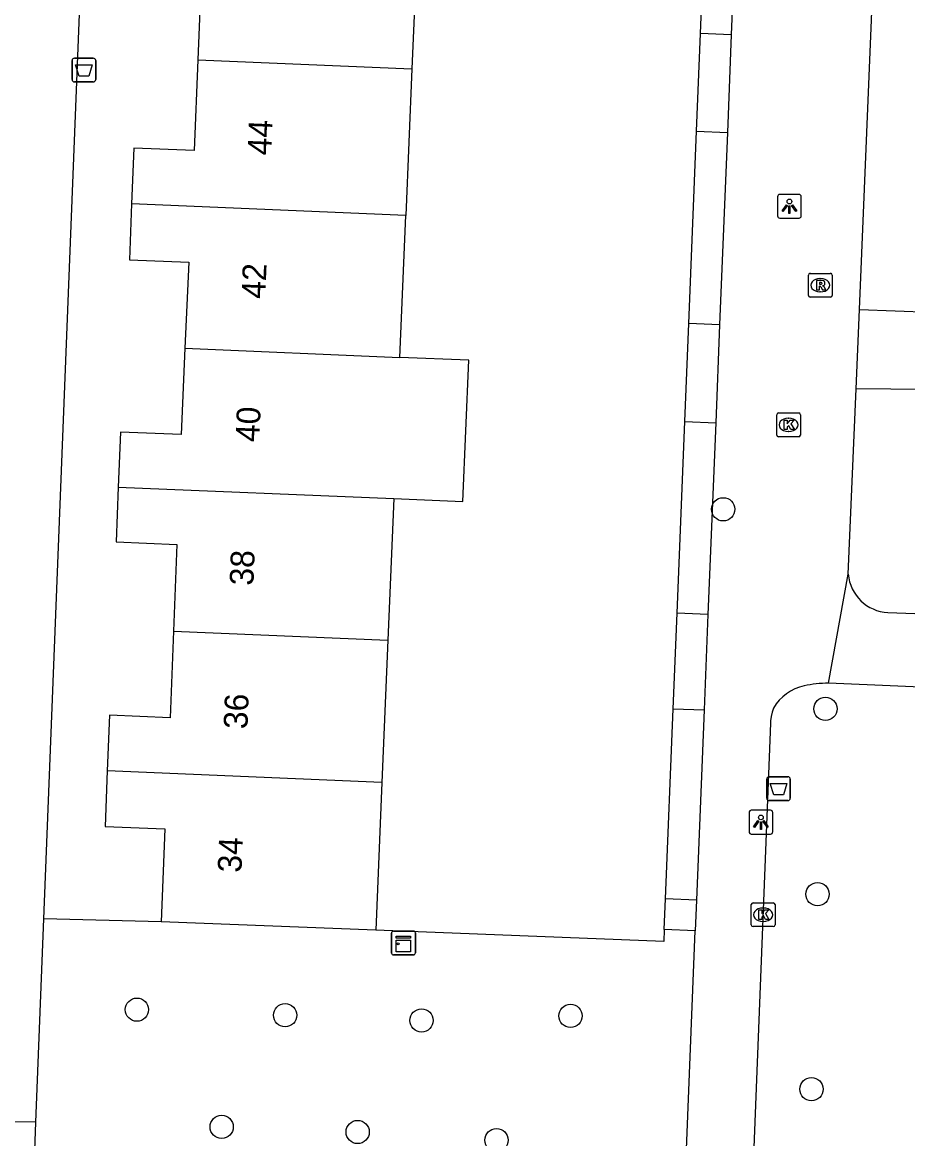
# Model space of a CAD drawing. Extents: x 160787 to 161428, y 386828 to 387483.
# Drawn here: x 161103.85 to 161141.08, y 387264.64 to 387311.59 of the extents above; entities that cross this region are included whole.
import ezdxf

# ---------------------------------------------------------------- set-up
doc = ezdxf.new("R2010")
doc.units = 0
for name, color, linetype in [('IMGEO_Afvalbak', 7, 'Continuous'), ('IMGEO_Boom', 7, 'Continuous'), ('IMGEO_Groenvoorziening', 7, 'Continuous'), ('IMGEO_Haag', 7, 'Continuous'), ('IMGEO_Kast', 7, 'Continuous'), ('IMGEO_Kolk', 7, 'Continuous'), ('IMGEO_Lichtpunt', 7, 'Continuous'), ('IMGEO_Pand', 7, 'Continuous'), ('IMGEO_Pand_nummerreeks', 7, 'Continuous'), ('IMGEO_Rioolput', 7, 'Continuous'), ('IMGEO_Voetpad_open', 7, 'Continuous')]:
    doc.layers.add(name, color=color, linetype=linetype)

msp = doc.modelspace()

# ---------------------------------------------------------------- linework, layer by layer
at = {"layer": 'IMGEO_Afvalbak'}
for p, q in [((161105.946, 387309.18), (161105.946, 387309.98)), ((161105.946, 387309.98), (161105.946, 387309.18)), ((161106.046, 387310.08), (161106.836, 387310.08)), ((161106.836, 387310.08), (161106.046, 387310.08)), ((161106.936, 387309.98), (161106.936, 387309.18)), ((161106.936, 387309.18), (161106.936, 387309.98)), ((161106.836, 387309.08), (161106.046, 387309.08)), ((161106.046, 387309.08), (161106.836, 387309.08)), ((161135.153, 387278.962), (161135.153, 387279.762)), ((161135.153, 387279.762), (161135.153, 387278.962)), ((161135.253, 387279.862), (161136.043, 387279.862)), ((161136.043, 387279.862), (161135.253, 387279.862)), ((161136.143, 387279.762), (161136.143, 387278.962)), ((161136.143, 387278.962), (161136.143, 387279.762)), ((161136.043, 387278.862), (161135.253, 387278.862)), ((161135.253, 387278.862), (161136.043, 387278.862))]:
    msp.add_line(p, q, dxfattribs=at)
for points in [[(161106.089, 387309.794), (161106.793, 387309.794), (161106.644, 387309.324), (161106.238, 387309.324), (161106.089, 387309.794)], [(161135.296, 387279.576), (161136, 387279.576), (161135.851, 387279.106), (161135.445, 387279.106), (161135.296, 387279.576)]]:
    msp.add_lwpolyline(points, dxfattribs=at)
for centre, start, end in [((161106.046, 387309.98), 90, 180), ((161106.046, 387309.98), 90, 180), ((161106.836, 387309.98), 0, 90), ((161106.836, 387309.98), 360, 90), ((161106.046, 387309.18), 180, 270), ((161106.046, 387309.18), 180, 270), ((161106.836, 387309.18), 270, 0), ((161106.836, 387309.18), 270, 0), ((161135.253, 387279.762), 90, 180), ((161135.253, 387279.762), 90, 180), ((161136.043, 387279.762), 0, 90), ((161136.043, 387279.762), 360, 90), ((161135.253, 387278.962), 180, 270), ((161135.253, 387278.962), 180, 270), ((161136.043, 387278.962), 270, 0), ((161136.043, 387278.962), 270, 0)]:
    msp.add_arc(centre, 0.1, start, end, dxfattribs=at)
at = {"layer": 'IMGEO_Boom'}
for centre in [(161133.321, 387291.109), (161137.619, 387282.717), (161137.288, 387274.923), (161108.67, 387270.067), (161114.902, 387269.831), (161120.638, 387269.615), (161126.901, 387269.805), (161137.032, 387266.723), (161112.233, 387265.138), (161117.951, 387264.922), (161123.79, 387264.578)]:
    msp.add_circle(centre, 0.489, dxfattribs=at)
at = {"layer": 'IMGEO_Groenvoorziening'}
for points in [[(161139.046, 387299.512), (161143.553, 387299.341), (161151.391, 387299.041)], [(161164.993, 387293.208), (161158.958, 387293.171), (161155.006, 387296.014), (161138.908, 387296.177)], [(161109.694, 387273.762), (161104.756, 387273.893)], [(161130.846, 387273.44), (161130.826, 387272.934), (161118.71, 387273.409)]]:
    msp.add_lwpolyline(points, dxfattribs=at)
at = {"layer": 'IMGEO_Haag'}
for points in [[(161132.363, 387311.119), (161132.69, 387319.253)], [(161131.872, 387298.919), (161132.197, 387307.013)], [(161131.382, 387286.74), (161131.706, 387294.803)], [(161130.898, 387274.729), (161131.22, 387282.723)]]:
    msp.add_lwpolyline(points, dxfattribs=at)
at = {"layer": 'IMGEO_Kast'}
for p, q in [((161119.377, 387272.447), (161119.377, 387273.288)), ((161119.377, 387273.288), (161119.377, 387272.447)), ((161119.452, 387273.372), (161120.293, 387273.372)), ((161120.293, 387273.372), (161119.452, 387273.372)), ((161120.377, 387273.297), (161120.377, 387272.456)), ((161120.377, 387272.456), (161120.377, 387273.297)), ((161120.302, 387272.372), (161119.461, 387272.372)), ((161119.461, 387272.372), (161120.302, 387272.372))]:
    msp.add_line(p, q, dxfattribs=at)
for points in [[(161119.572, 387273.162), (161120.172, 387273.162), (161120.172, 387273.077), (161119.572, 387273.077), (161119.572, 387273.162)], [(161119.572, 387272.987), (161120.172, 387272.987), (161120.172, 387272.498), (161119.572, 387272.498), (161119.572, 387272.987)]]:
    msp.add_lwpolyline(points, dxfattribs=at)
msp.add_circle((161119.656, 387272.836), 0.0377, dxfattribs=at)
for centre, start, end in [((161119.455, 387273.294), 92.4484, 184.2845), ((161119.455, 387273.294), 92.4484, 184.2845), ((161120.299, 387273.294), 2.4484, 94.2845), ((161120.299, 387273.294), 2.4484, 94.2845), ((161119.455, 387272.45), 182.4484, 274.2845), ((161119.455, 387272.45), 182.4484, 274.2845), ((161120.299, 387272.45), 272.4484, 4.2845), ((161120.299, 387272.45), 272.4484, 4.2845)]:
    msp.add_arc(centre, 0.0779, start, end, dxfattribs=at)
at = {"layer": 'IMGEO_Kolk'}
for p, q in [((161135.57, 387294.233), (161135.57, 387295.085)), ((161135.645, 387295.159), (161136.497, 387295.159)), ((161136.058, 387294.939), (161136.083, 387294.939)), ((161136.571, 387295.085), (161136.571, 387294.233)), ((161136.081, 387294.379), (161136.056, 387294.379)), ((161136.497, 387294.159), (161135.645, 387294.159)), ((161134.576, 387274.559), (161135.428, 387274.559)), ((161134.501, 387273.633), (161134.501, 387274.485)), ((161134.989, 387274.339), (161135.014, 387274.339)), ((161135.502, 387274.485), (161135.502, 387273.633)), ((161135.012, 387273.779), (161134.987, 387273.779)), ((161135.428, 387273.559), (161134.576, 387273.559))]:
    msp.add_line(p, q, dxfattribs=at)
for points in [[(161135.57, 387294.233), (161135.57, 387295.085)], [(161135.645, 387295.159), (161136.497, 387295.159)], [(161135.891, 387294.859), (161136.014, 387294.859), (161136.014, 387294.708), (161136.144, 387294.859), (161136.308, 387294.859), (161136.162, 387294.708), (161136.315, 387294.459), (161136.163, 387294.459), (161136.078, 387294.623), (161136.014, 387294.556), (161136.014, 387294.459), (161135.891, 387294.459), (161135.891, 387294.859)], [(161136.571, 387295.085), (161136.571, 387294.233)], [(161136.497, 387294.159), (161135.645, 387294.159)], [(161134.576, 387274.559), (161135.428, 387274.559)], [(161134.501, 387273.633), (161134.501, 387274.485)], [(161134.822, 387274.259), (161134.945, 387274.259), (161134.945, 387274.108), (161135.075, 387274.259), (161135.239, 387274.259), (161135.093, 387274.108), (161135.246, 387273.859), (161135.094, 387273.859), (161135.009, 387274.023), (161134.945, 387273.956), (161134.945, 387273.859), (161134.822, 387273.859), (161134.822, 387274.259)], [(161135.502, 387274.485), (161135.502, 387273.633)], [(161135.428, 387273.559), (161134.576, 387273.559)]]:
    msp.add_lwpolyline(points, dxfattribs=at)
for centre, start, end in [((161135.647, 387295.083), 91.552, 178.448), ((161135.647, 387295.083), 91.552, 178.448), ((161136.495, 387295.083), 1.552, 88.448), ((161136.495, 387295.083), 1.552, 88.448), ((161135.647, 387294.235), 181.552, 268.448), ((161135.647, 387294.235), 181.552, 268.448), ((161136.495, 387294.235), 271.552, 358.448), ((161136.495, 387294.235), 271.552, 358.448), ((161134.578, 387274.483), 91.552, 178.448), ((161134.578, 387274.483), 91.552, 178.448), ((161135.426, 387274.483), 1.552, 88.448), ((161135.426, 387274.483), 1.552, 88.448), ((161134.578, 387273.635), 181.552, 268.448), ((161134.578, 387273.635), 181.552, 268.448), ((161135.426, 387273.635), 271.552, 358.448), ((161135.426, 387273.635), 271.552, 358.448)]:
    msp.add_arc(centre, 0.0765, start, end, dxfattribs=at)
for centre, major_axis, ratio, start_param, end_param in [((161136.057, 387294.659), (-0.387, 0.002), 0.722429, 4.712389, 7.853982), ((161136.082, 387294.659), (-0.39, 0.002), 0.717154, 1.570796, 4.712389), ((161134.988, 387274.059), (-0.387, 0.002), 0.722429, 4.712389, 7.853982), ((161135.013, 387274.059), (-0.39, 0.002), 0.717154, 1.570796, 4.712389)]:
    msp.add_ellipse(centre, major_axis=major_axis, ratio=ratio, start_param=start_param, end_param=end_param, dxfattribs=at)
at = {"layer": 'IMGEO_Lichtpunt'}
for p, q in [((161135.607, 387304.255), (161135.607, 387303.448)), ((161135.607, 387304.255), (161135.607, 387303.448)), ((161136.509, 387304.35), (161135.701, 387304.35)), ((161136.509, 387304.35), (161135.701, 387304.35)), ((161136.603, 387303.448), (161136.603, 387304.255)), ((161136.603, 387303.448), (161136.603, 387304.255)), ((161135.701, 387303.354), (161136.509, 387303.354)), ((161135.701, 387303.354), (161136.509, 387303.354)), ((161134.408, 387278.355), (161134.408, 387277.548)), ((161134.408, 387278.355), (161134.408, 387277.548)), ((161135.31, 387278.45), (161134.502, 387278.45)), ((161135.31, 387278.45), (161134.502, 387278.45)), ((161135.404, 387277.548), (161135.404, 387278.355)), ((161135.404, 387277.548), (161135.404, 387278.355)), ((161134.502, 387277.454), (161135.31, 387277.454)), ((161134.502, 387277.454), (161135.31, 387277.454))]:
    msp.add_line(p, q, dxfattribs=at)
for points in [[(161135.981, 387303.919), (161136.02, 387303.891), (161135.832, 387303.629), (161135.794, 387303.656), (161135.981, 387303.919)], [(161136.083, 387303.871), (161136.13, 387303.871), (161136.13, 387303.549), (161136.083, 387303.549), (161136.083, 387303.871)], [(161136.193, 387303.891), (161136.231, 387303.918), (161136.418, 387303.656), (161136.379, 387303.628), (161136.193, 387303.891)], [(161134.782, 387278.019), (161134.821, 387277.991), (161134.633, 387277.729), (161134.595, 387277.756), (161134.782, 387278.019)], [(161134.884, 387277.971), (161134.931, 387277.971), (161134.931, 387277.649), (161134.884, 387277.649), (161134.884, 387277.971)], [(161134.994, 387277.991), (161135.032, 387278.018), (161135.219, 387277.756), (161135.18, 387277.728), (161134.994, 387277.991)]]:
    msp.add_lwpolyline(points, dxfattribs=at)
for centre in [(161136.106, 387304.053), (161134.907, 387278.153)]:
    msp.add_circle(centre, 0.0994, dxfattribs=at)
for centre, start, end in [((161135.701, 387304.255), 90, 180), ((161135.701, 387304.255), 90, 180), ((161136.509, 387304.255), 0, 90), ((161136.509, 387304.255), 0, 90), ((161135.701, 387303.448), 180, 270), ((161135.701, 387303.448), 180, 270), ((161136.509, 387303.448), 270, 0), ((161136.509, 387303.448), 270, 360), ((161134.502, 387278.355), 90, 180), ((161134.502, 387278.355), 90, 180), ((161135.31, 387278.355), 0, 90), ((161135.31, 387278.355), 0, 90), ((161134.502, 387277.548), 180, 270), ((161134.502, 387277.548), 180, 270), ((161135.31, 387277.548), 270, 0), ((161135.31, 387277.548), 270, 360)]:
    msp.add_arc(centre, 0.0946, start, end, dxfattribs=at)
at = {"layer": 'IMGEO_Pand'}
for points in [[(161108.982, 387316.222), (161108.89, 387313.938), (161111.382, 387313.838), (161111.228, 387310.015)], [(161120.493, 387315.737), (161120.236, 387309.635)], [(161111.228, 387310.015), (161111.074, 387306.191), (161108.542, 387306.293), (161108.448, 387303.95)], [(161111.228, 387310.015), (161120.236, 387309.635)], [(161120.236, 387309.635), (161119.976, 387303.464)], [(161108.448, 387303.95), (161108.353, 387301.603), (161110.848, 387301.503), (161110.687, 387297.88)], [(161119.976, 387303.464), (161108.448, 387303.95)], [(161119.725, 387297.499), (161119.976, 387303.464)], [(161110.687, 387297.88), (161110.526, 387294.256), (161107.976, 387294.356), (161107.885, 387292.045)], [(161110.687, 387297.88), (161119.725, 387297.499)], [(161119.474, 387291.557), (161122.377, 387291.435), (161122.627, 387297.377), (161119.725, 387297.499)], [(161107.885, 387292.045), (161107.795, 387289.734), (161110.35, 387289.634), (161110.208, 387285.99)], [(161107.885, 387292.045), (161119.474, 387291.557)], [(161119.474, 387291.557), (161119.224, 387285.61)], [(161110.208, 387285.99), (161110.065, 387282.345), (161107.511, 387282.445), (161107.42, 387280.108)], [(161110.208, 387285.99), (161119.224, 387285.61)], [(161119.224, 387285.61), (161118.972, 387279.621)], [(161107.42, 387280.108), (161107.328, 387277.768), (161109.847, 387277.67), (161109.694, 387273.762)], [(161118.972, 387279.621), (161107.42, 387280.108)], [(161118.972, 387279.621), (161118.71, 387273.409)], [(161118.71, 387273.409), (161109.694, 387273.762)]]:
    msp.add_lwpolyline(points, dxfattribs=at)
at = {"layer": 'IMGEO_Rioolput'}
for p, q in [((161136.903, 387300.106), (161136.903, 387300.958)), ((161136.978, 387301.032), (161137.83, 387301.032)), ((161137.904, 387300.958), (161137.904, 387300.106)), ((161137.391, 387300.812), (161137.416, 387300.812)), ((161137.83, 387300.032), (161136.978, 387300.032)), ((161137.414, 387300.252), (161137.389, 387300.252))]:
    msp.add_line(p, q, dxfattribs=at)
for points in [[(161136.903, 387300.106), (161136.903, 387300.958)], [(161136.978, 387301.032), (161137.83, 387301.032)], [(161137.904, 387300.958), (161137.904, 387300.106)], [(161137.492, 387300.73), (161137.24, 387300.732), (161137.24, 387300.332)], [(161137.24, 387300.332), (161137.364, 387300.332), (161137.364, 387300.494), (161137.375, 387300.494)], [(161137.418, 387300.651), (161137.364, 387300.651), (161137.364, 387300.57)], [(161137.364, 387300.57), (161137.416, 387300.57)], [(161137.422, 387300.465), (161137.493, 387300.332), (161137.633, 387300.332), (161137.568, 387300.458)], [(161137.83, 387300.032), (161136.978, 387300.032)]]:
    msp.add_lwpolyline(points, dxfattribs=at)
for centre, radius, start, end in [((161136.98, 387300.956), 0.0765, 91.552, 178.448), ((161136.98, 387300.956), 0.0765, 91.552, 178.448), ((161137.828, 387300.956), 0.0765, 1.552, 88.448), ((161137.828, 387300.956), 0.0765, 1.552, 88.448), ((161137.374, 387300.441), 0.0533, 26.0293, 88.6989), ((161137.4, 387300.759), 0.19, 274.7715, 282.9687), ((161137.424, 387300.555), 0.0964, 77.0061, 93.1865), ((161137.438, 387300.612), 0.0378, 276.6634, 79.6772), ((161137.491, 387300.62), 0.109, 350.3612, 89.416), ((161137.489, 387300.62), 0.112, 277.5842, 350.9817), ((161137.473, 387300.405), 0.108, 29.5134, 73.7905), ((161136.98, 387300.108), 0.0765, 181.552, 268.448), ((161136.98, 387300.108), 0.0765, 181.552, 268.448), ((161137.828, 387300.108), 0.0765, 271.552, 358.448), ((161137.828, 387300.108), 0.0765, 271.552, 358.448)]:
    msp.add_arc(centre, radius, start, end, dxfattribs=at)
for centre, major_axis, ratio, start_param, end_param in [((161137.39, 387300.532), (-0.387, 0.002), 0.722429, 4.712389, 7.853982), ((161137.415, 387300.532), (-0.39, 0.002), 0.717154, 1.570796, 4.712389)]:
    msp.add_ellipse(centre, major_axis=major_axis, ratio=ratio, start_param=start_param, end_param=end_param, dxfattribs=at)
at = {"layer": 'IMGEO_Voetpad_open'}
for points in [[(161139.046, 387299.512), (161142.214, 387375.996), (161142.215, 387376.018), (161142.294, 387377.909)], [(161133.989, 387319.201), (161133.662, 387311.067)], [(161104.756, 387273.893), (161106.267, 387312.29)], [(161132.197, 387307.013), (161132.363, 387311.119)], [(161133.662, 387311.067), (161132.363, 387311.119)], [(161133.662, 387311.067), (161133.497, 387306.961)], [(161132.197, 387307.013), (161133.497, 387306.961)], [(161133.497, 387306.961), (161133.171, 387298.867)], [(161138.908, 387296.177), (161139.046, 387299.512)], [(161131.706, 387294.803), (161131.872, 387298.919)], [(161133.171, 387298.867), (161131.872, 387298.919)], [(161133.171, 387298.867), (161133.005, 387294.751)], [(161138.578, 387288.383), (161138.908, 387296.177)], [(161131.706, 387294.803), (161133.005, 387294.751)], [(161133.005, 387294.751), (161132.681, 387286.688)], [(161137.745, 387283.796), (161138.578, 387288.383)], [(161140.247, 387286.767), (161162.637, 387285.947), (161163.314, 387285.947), (161163.563, 387285.964), (161163.803, 387285.99)], [(161131.22, 387282.723), (161131.382, 387286.74)], [(161132.681, 387286.688), (161131.382, 387286.74)], [(161132.681, 387286.688), (161132.519, 387282.671)], [(161143.258, 387283.56), (161137.745, 387283.796)], [(161131.22, 387282.723), (161132.519, 387282.671)], [(161135.431, 387282.75), (161135.375, 387282.575), (161135.335, 387282.396), (161135.31, 387282.213), (161135.304, 387282.111), (161134.046, 387250), (161131.872, 387194.508), (161131.578, 387188.533)], [(161132.519, 387282.671), (161132.198, 387274.677)], [(161130.846, 387273.44), (161130.898, 387274.729)], [(161132.198, 387274.677), (161130.898, 387274.729)], [(161132.198, 387274.677), (161132.146, 387273.388)], [(161104.419, 387265.337), (161104.756, 387273.893)], [(161132.146, 387273.388), (161130.846, 387273.44)], [(161131.733, 387263.132), (161132.146, 387273.388)], [(161104.419, 387265.337), (161099.828, 387265.381)], [(161129.803, 387261.24), (161106.195, 387262.173), (161106.096, 387262.179), (161105.928, 387262.202), (161105.763, 387262.24), (161105.601, 387262.292), (161105.445, 387262.359), (161105.296, 387262.439), (161105.154, 387262.532), (161105.022, 387262.638), (161104.899, 387262.755), (161104.787, 387262.882), (161104.687, 387263.019), (161104.6, 387263.164), (161104.526, 387263.317), (161104.465, 387263.476), (161104.42, 387263.639), (161104.389, 387263.806), (161104.373, 387263.974), (161104.372, 387264.144), (161104.419, 387265.337)]]:
    msp.add_lwpolyline(points, dxfattribs=at)
for centre, radius, start, end in [((161140.345, 387288.538), 1.774, 185.0156, 266.8331), ((161137.172, 387281.713), 2.027, 102.6102, 149.2292), ((161137.866, 387277.667), 6.13, 91.1319, 100.6804)]:
    msp.add_arc(centre, radius, start, end, dxfattribs=at)

# ---------------------------------------------------------------- texts
at = {"layer": 'IMGEO_Pand_nummerreeks'}
for s, rotation, p in [('44', 87.6236, (161114.314, 387305.983)), ('42', 87.6236, (161114.063, 387299.947)), ('40', 87.6224, (161113.814, 387293.92)), ('38', 87.6236, (161113.563, 387287.887)), ('36', 87.6236, (161113.312, 387281.851)), ('34', 87.6236, (161113.062, 387275.817))]:
    msp.add_text(s, height=1, rotation=rotation, dxfattribs=at).set_placement(p)

doc.saveas('drawing.dxf')
